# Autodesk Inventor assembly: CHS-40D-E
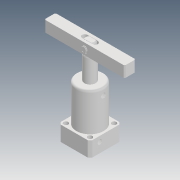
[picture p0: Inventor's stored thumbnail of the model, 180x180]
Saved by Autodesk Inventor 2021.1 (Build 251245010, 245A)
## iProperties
Created: 2019-04
Part Number: CHS-40D-E
Description: STEP AP203
Document SubType Name: Assembly
Designer: user
Title: chs-40d-e_asm.STEP
Revision Number: ÈÎºÎ
Sending System: SolidWorks 2017
Preprocessor: SwSTEP 2.0
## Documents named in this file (6)
- D:\Vault_2016\Projekty\Clamptek\Hydraulic\CHS\CHS-40\Inventor\CHS-40D-E\CHS-40D-E.iam
- D:\Vault_2016\Projekty\Clamptek\Hydraulic\CHS\CHS-40\Inventor\CHS-40D-E\CHS-40-03-E.ipt
- D:\Vault_2016\Projekty\Clamptek\Hydraulic\CHS\CHS-40\Inventor\CHS-40D-E\CHS-40D-02-E.ipt
- D:\Vault_2016\Projekty\Clamptek\Hydraulic\CHS\CHS-40\Inventor\CHS-40D-E\CHS-40D-01_1.ipt
- D:\Vault_2016\Projekty\Clamptek\Hydraulic\CHS\CHS-40\Inventor\CHS-40D-E\XIAO.ipt
- D:\Vault_2016\Projekty\Clamptek\Hydraulic\CHS\CHS-40\Inventor\CHS-40D-E\12ÖáÓÃµ²È¦.ipt
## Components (6 placed, 6 different names)
1. CHS-40-03-E_1
2. CHS-40D-02-E_2
3. CHS-40D-01_1_3
4. XIAO_4
5. 12ÖáÓÃµ²È¦_5
6. 12ÖáÓÃµ²È¦_6
